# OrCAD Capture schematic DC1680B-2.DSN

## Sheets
1 Mother Board_Daughter Connect: size Custom
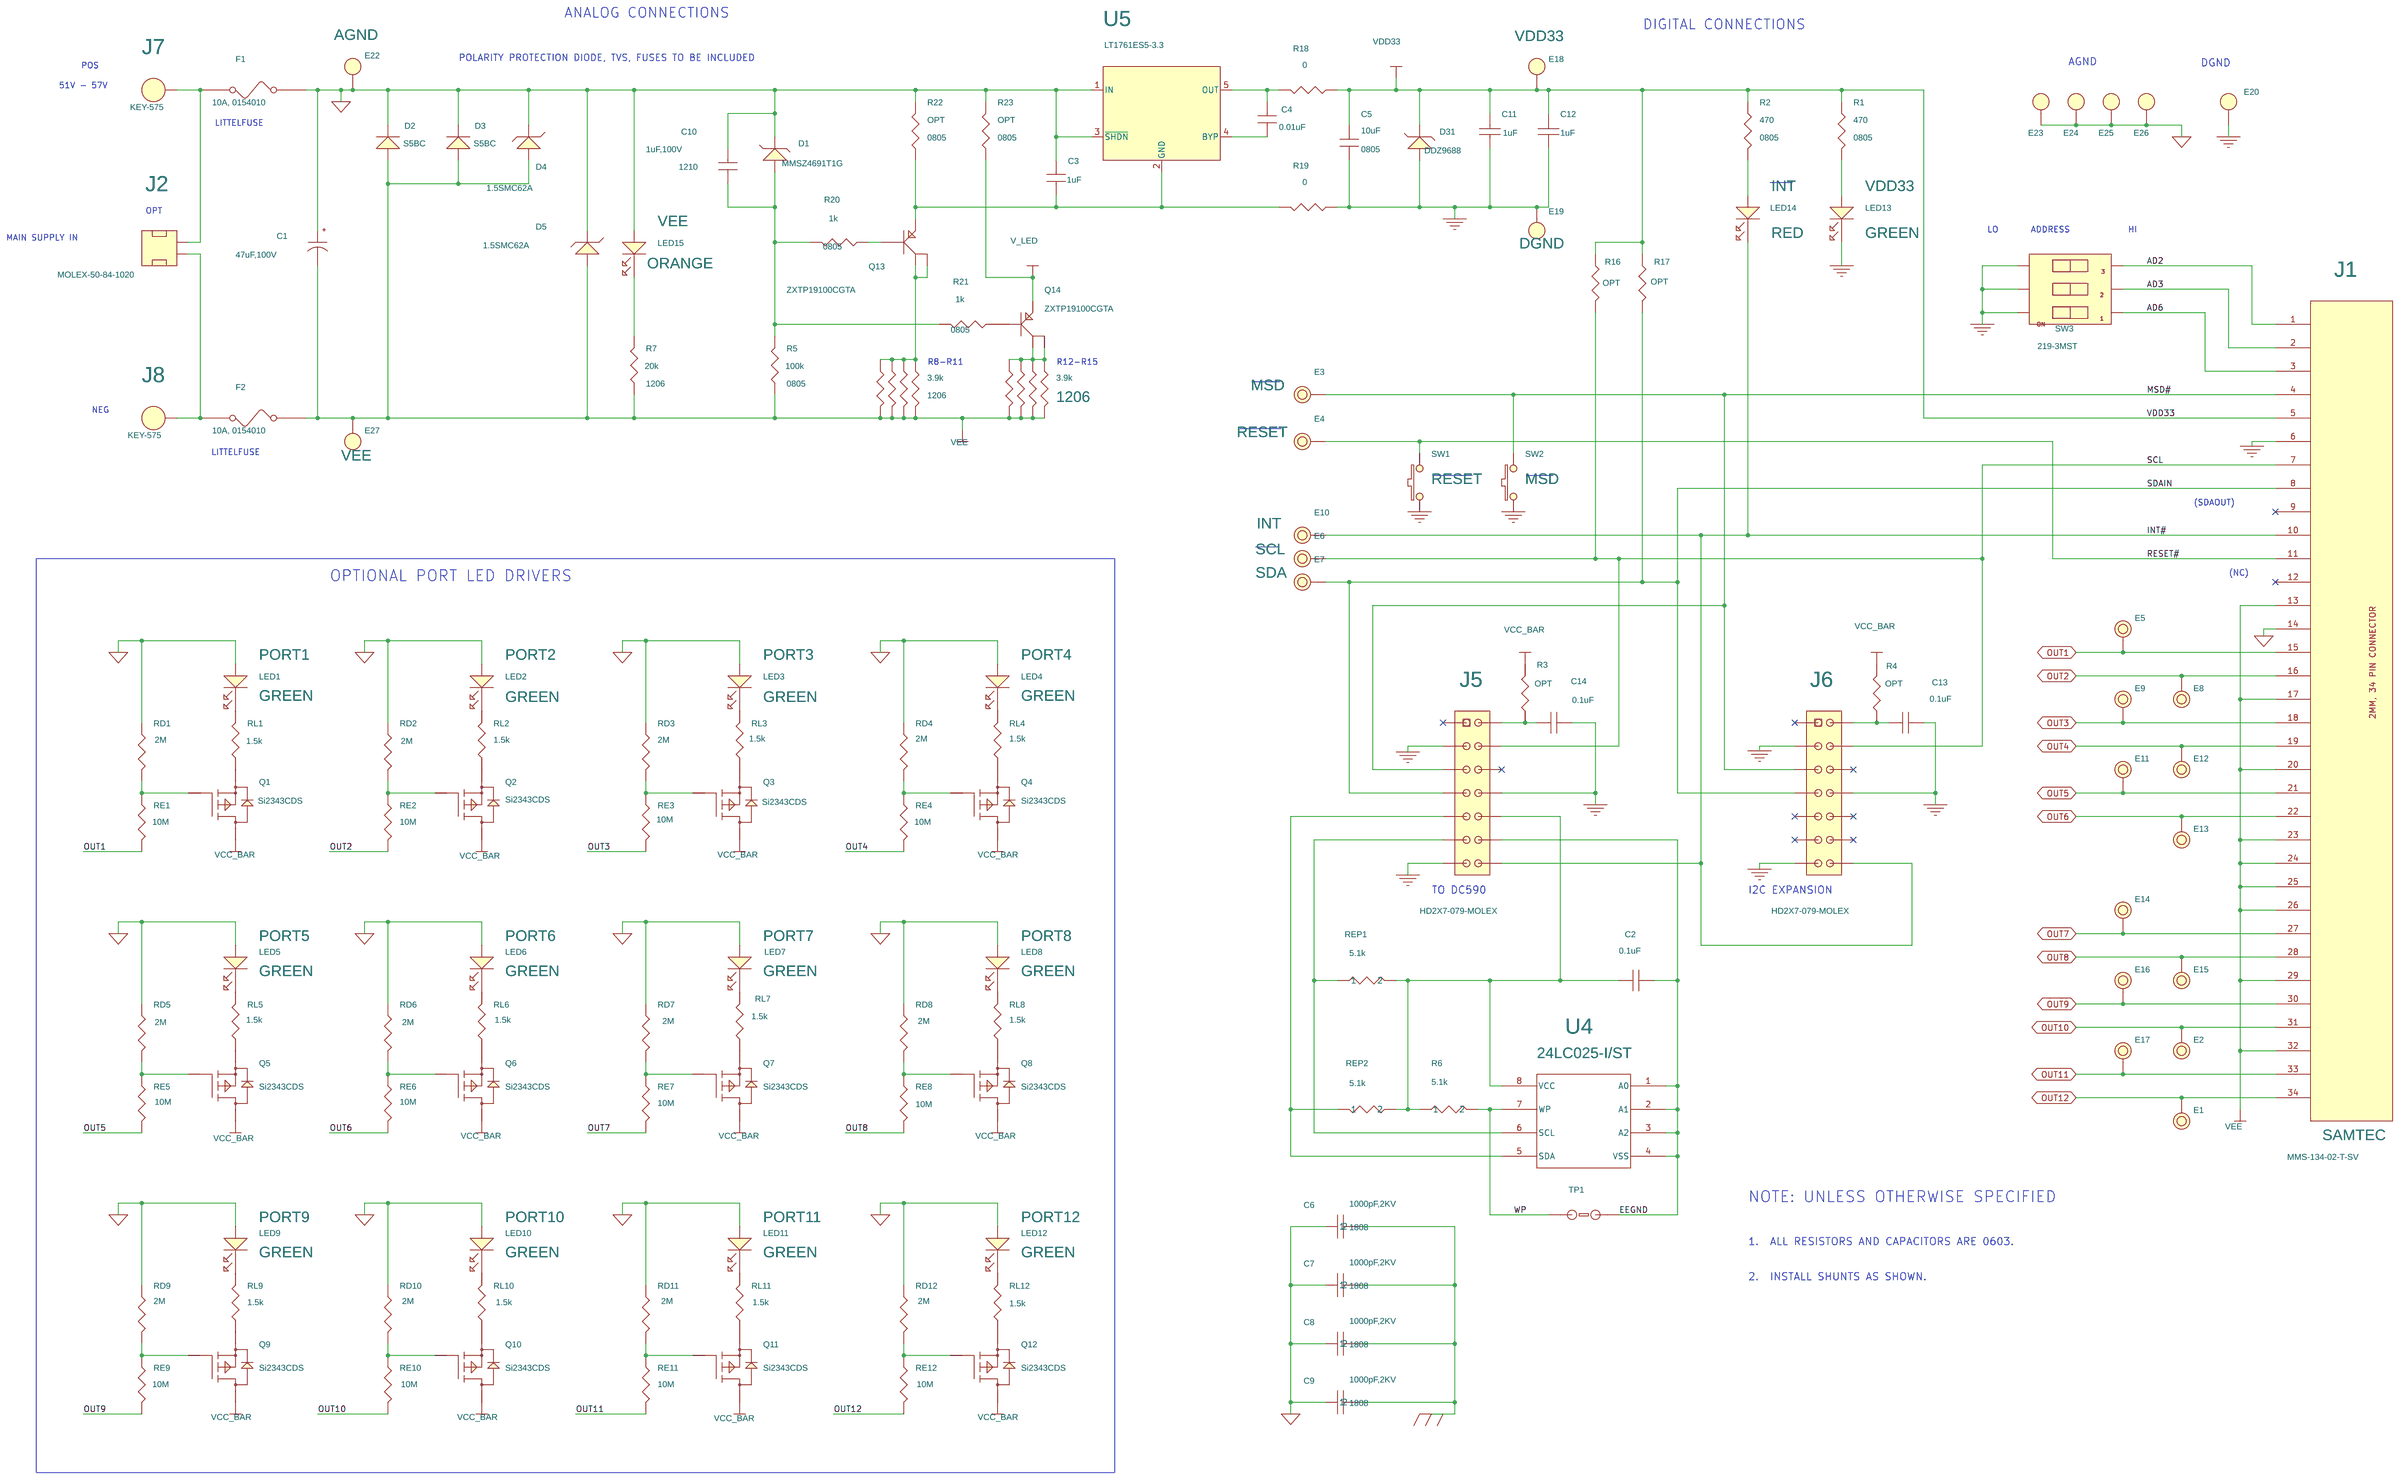
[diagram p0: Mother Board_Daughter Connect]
2 Ports 1 to 4 Jacks: size Custom; title: 12-PORT IEEE802.3at PSE MOTHER BOARD; rev: 2; note: DEMO CIRCUIT 1680B
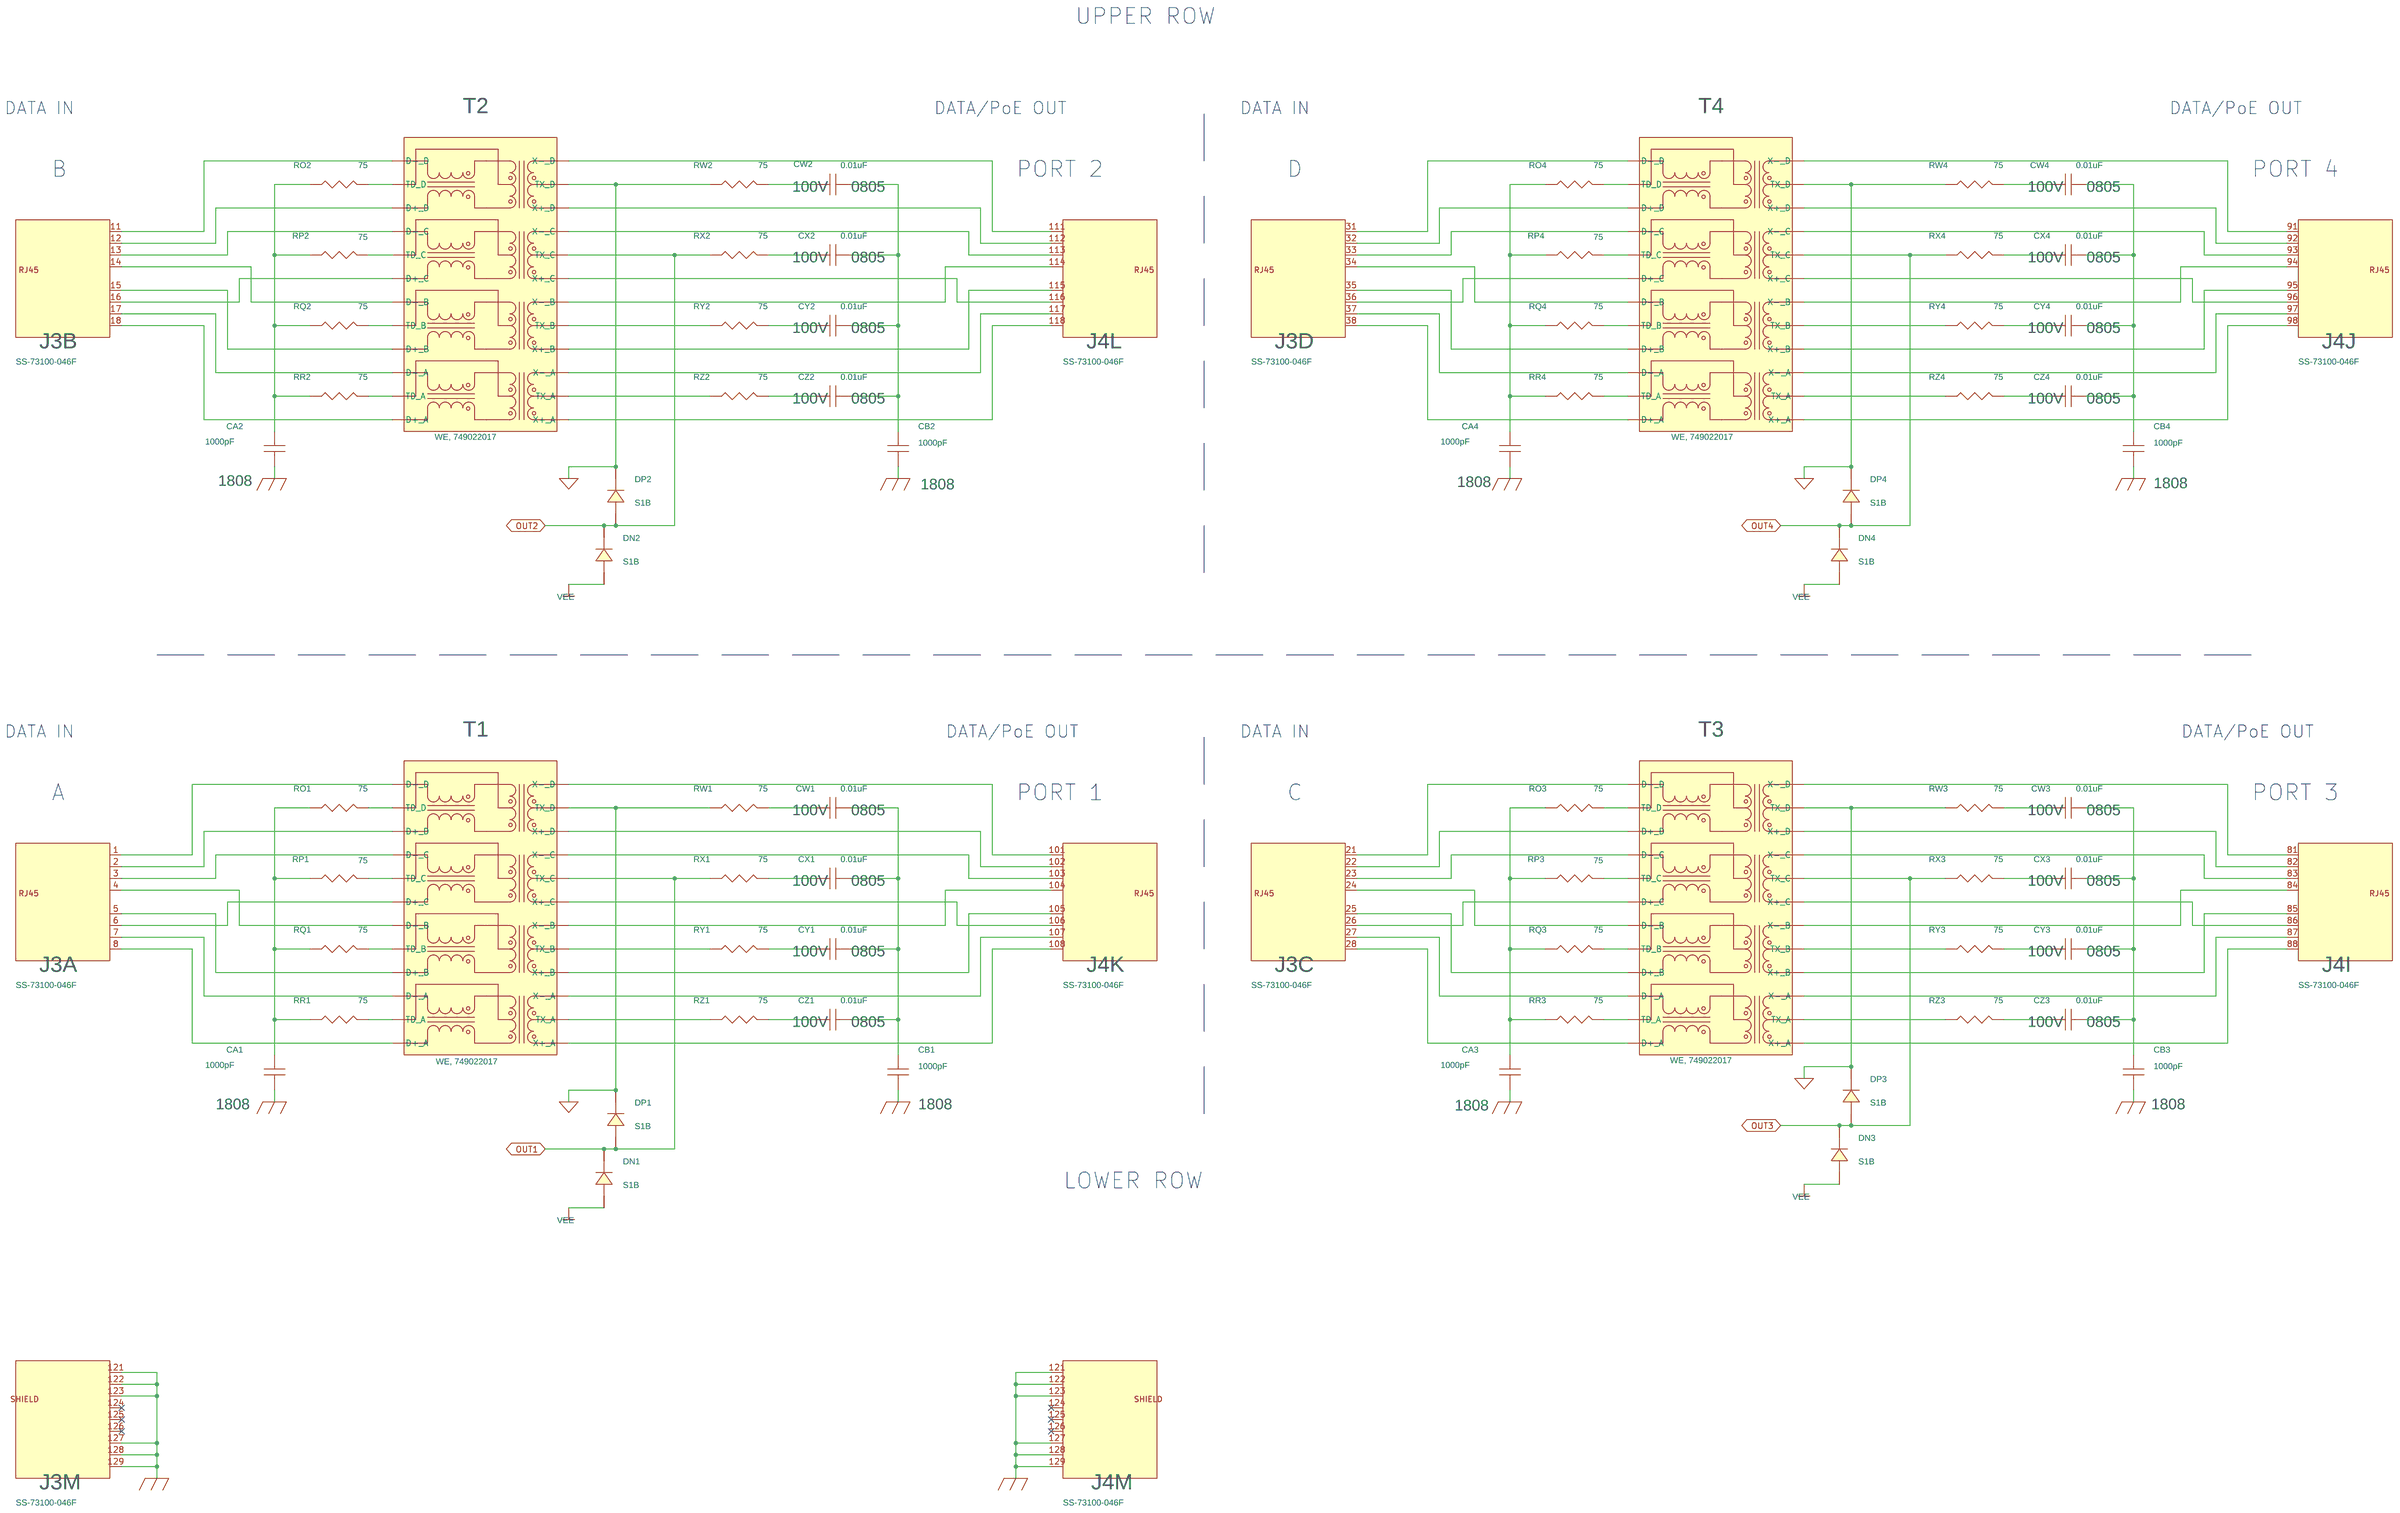
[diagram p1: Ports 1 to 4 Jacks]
3 Ports 5 to 8 Jacks: size Custom; title: 12-PORT IEEE802.3at PSE MOTHER BOARD; rev: 2; note: DEMO CIRCUIT 1680B
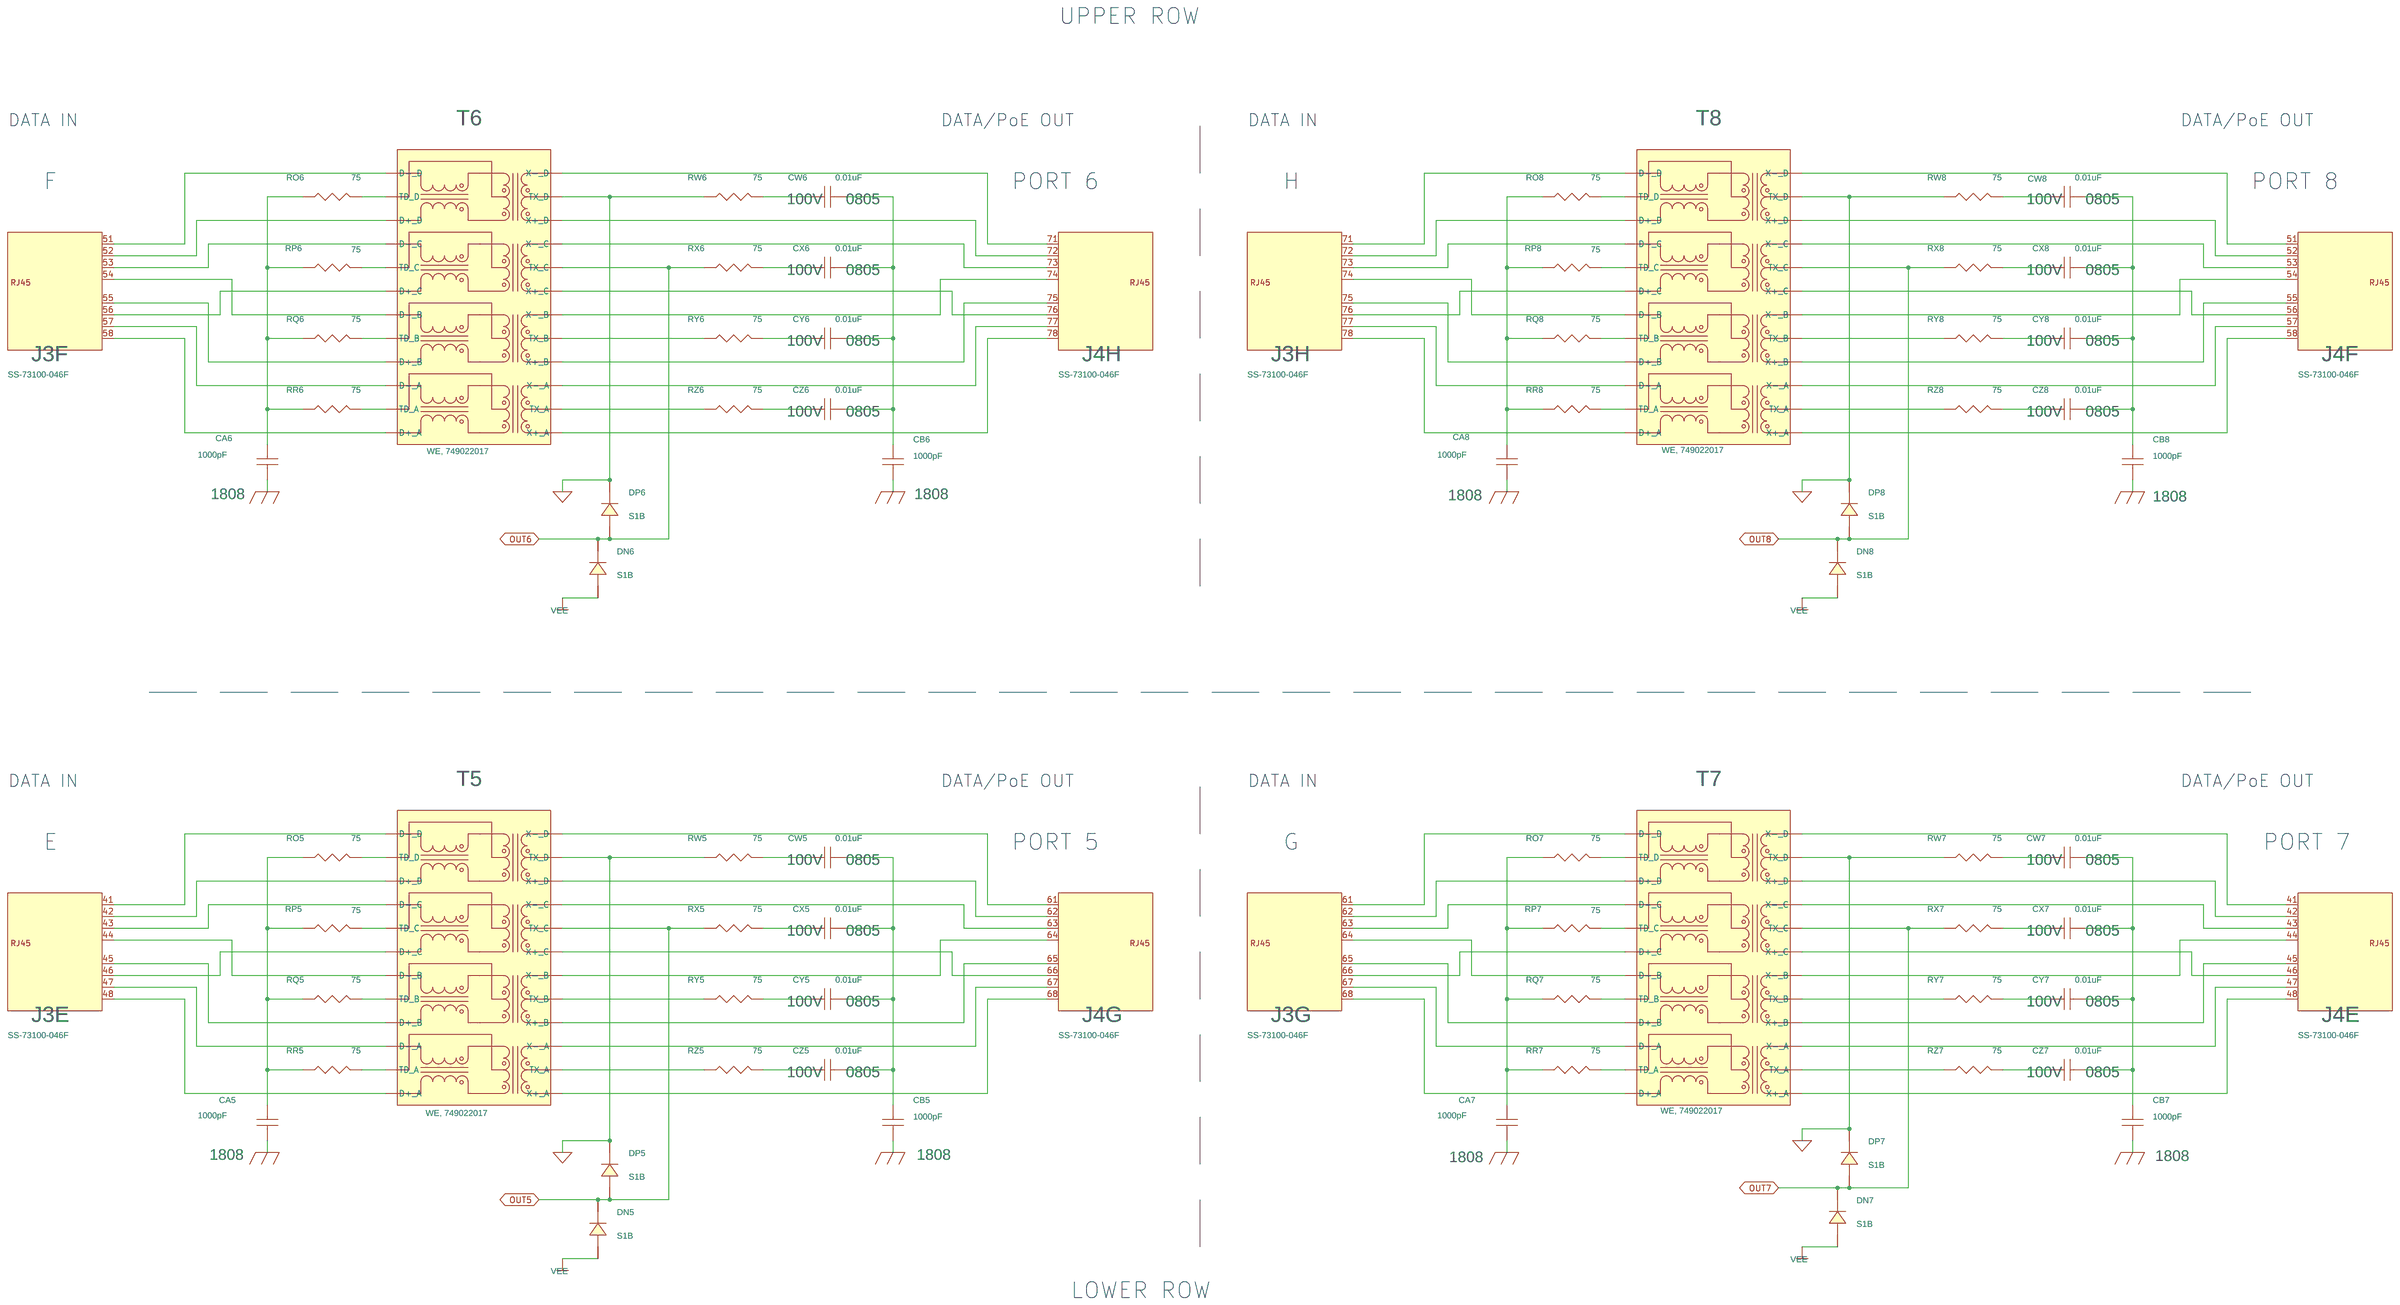
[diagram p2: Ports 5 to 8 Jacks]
4 Ports 9 to 12 Jacks: size Custom; title: 12-PORT IEEE802.3at PSE MOTHER BOARD; rev: 2; note: DEMO CIRCUIT 1680B
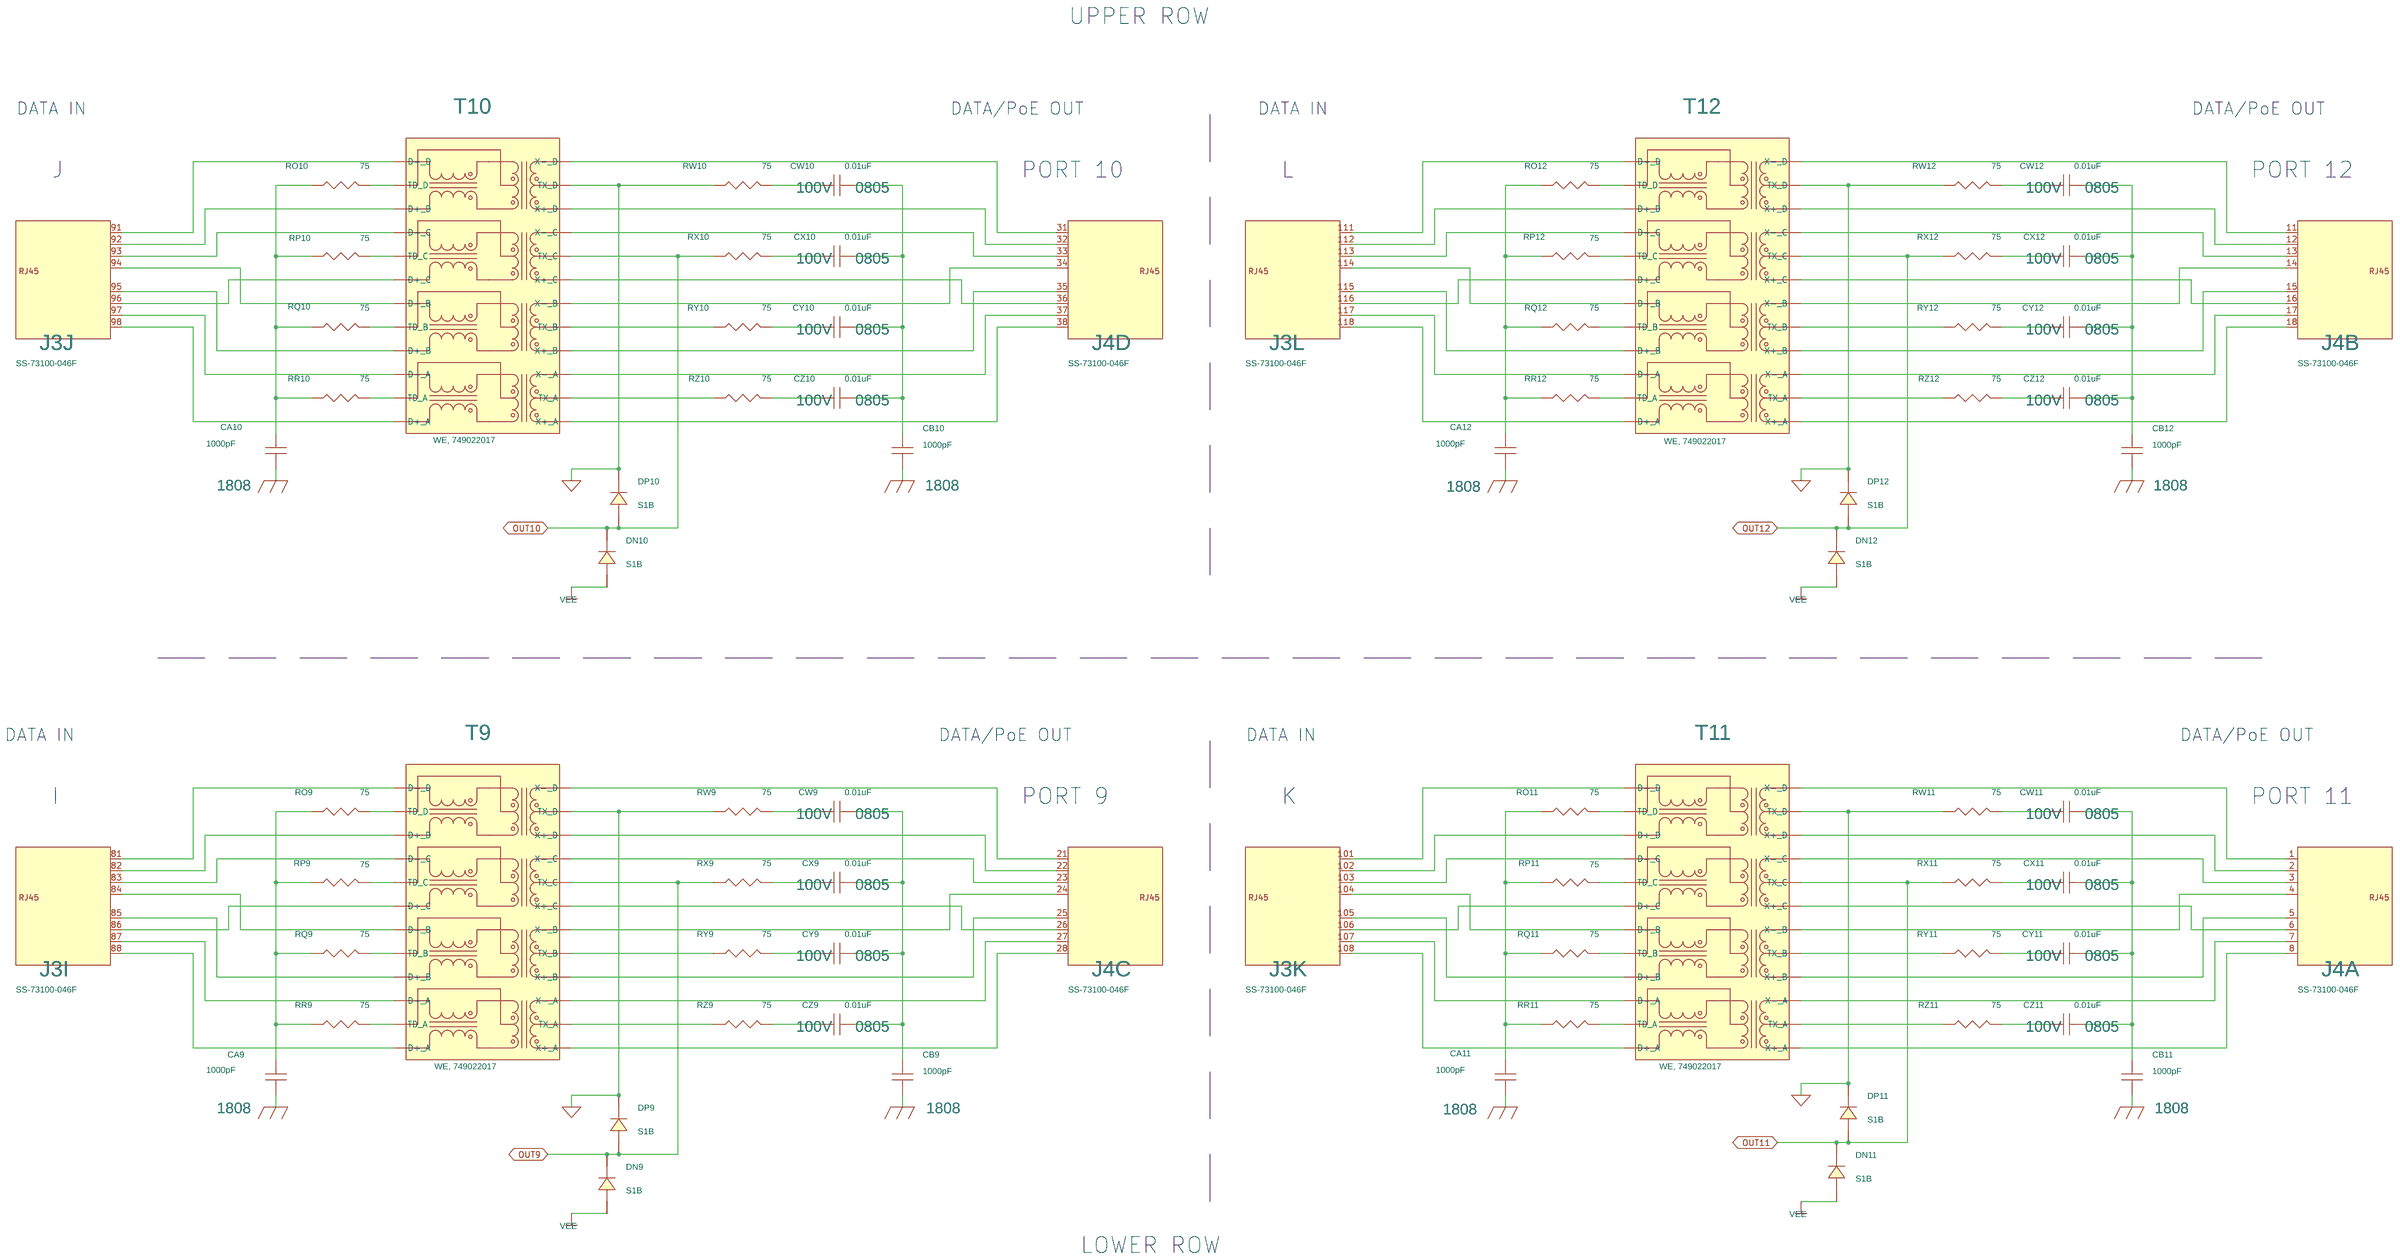
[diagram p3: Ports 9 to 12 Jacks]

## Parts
sheet Mother Board_Daughter Connect
C1  47uF,100V  [C-PANA-H13-12.5X13.5]
C2  0.1uF  [0603]
C3  1uF  [0603]
C4  0.01uF  [0603]
C5  10uF  [0805]
C6  1000pF,2KV  [1808]
C7  1000pF,2KV  [1808]
C8  1000pF,2KV  [1808]
C9  1000pF,2KV  [1808]
C10  1uF,100V  [1210]
C11  1uF  [0603]
C12  1uF  [0603]
C13  0.1uF  [0603]
C14  0.1uF  [0603]
D1  MMSZ4691T1G  [SOD123]
D2  S5BC  [SMC-DIODE]
D3  S5BC  [SMC-DIODE]
D4  1.5SMC62A  [SMC-DIODE]
D5  1.5SMC62A  [SMC-DIODE]
D31  DDZ9688  [SOD123]
E1  MILL-MAX-2308  [MILL-MAX-2308]
E2  MILL-MAX-2308  [MILL-MAX-2308]
E3  MILL-MAX-2308  [MILL-MAX-2308]
E4  MILL-MAX-2308  [MILL-MAX-2308]
E5  MILL-MAX-2308  [MILL-MAX-2308]
E6  MILL-MAX-2308  [MILL-MAX-2308]
E7  MILL-MAX-2308  [MILL-MAX-2308]
E8  MILL-MAX-2308  [MILL-MAX-2308]
E9  MILL-MAX-2308  [MILL-MAX-2308]
E10  MILL-MAX-2308  [MILL-MAX-2308]
E11  MILL-MAX-2308  [MILL-MAX-2308]
E12  MILL-MAX-2308  [MILL-MAX-2308]
E13  MILL-MAX-2308  [MILL-MAX-2308]
E14  MILL-MAX-2308  [MILL-MAX-2308]
E15  MILL-MAX-2308  [MILL-MAX-2308]
E16  MILL-MAX-2308  [MILL-MAX-2308]
E17  MILL-MAX-2308  [MILL-MAX-2308]
E18  MILL-MAX-2501  [MILL-MAX-2501]
E19  MILL-MAX-2501  [MILL-MAX-2501]
E20  MILL-MAX-2501  [MILL-MAX-2501]
E22  MILL-MAX-2501  [MILL-MAX-2501]
E23  MILL-MAX-2501  [MILL-MAX-2501]
E24  MILL-MAX-2501  [MILL-MAX-2501]
E25  MILL-MAX-2501  [MILL-MAX-2501]
E26  MILL-MAX-2501  [MILL-MAX-2501]
E27  MILL-MAX-2501  [MILL-MAX-2501]
F1  10A, 0154010  [FUSE-LITTELFUSE-154]
F2  10A, 0154010  [FUSE-LITTELFUSE-154]
J1  MMS-134-02-T-SV  [CON-MMS-134-02-T-SV]
J2  MOLEX-50-84-1020  [CON-MOLEX-50-84-1020]
J5  HD2X7-079-MOLEX  [HD2X7-079-MOLEX]
J6  HD2X7-079-MOLEX  [HD2X7-079-MOLEX]
J7  KEY-575  [KEY-575]
J8  KEY-575  [KEY-575]
LED1  SML-012P8T  [LED-ROHM-SML-01]
LED2  SML-012P8T  [LED-ROHM-SML-01]
LED3  SML-012P8T  [LED-ROHM-SML-01]
LED4  SML-012P8T  [LED-ROHM-SML-01]
LED5  SML-012P8T  [LED-ROHM-SML-01]
LED6  SML-012P8T  [LED-ROHM-SML-01]
LED7  SML-012P8T  [LED-ROHM-SML-01]
LED8  SML-012P8T  [LED-ROHM-SML-01]
LED9  SML-012P8T  [LED-ROHM-SML-01]
LED10  SML-012P8T  [LED-ROHM-SML-01]
LED11  SML-012P8T  [LED-ROHM-SML-01]
LED12  SML-012P8T  [LED-ROHM-SML-01]
LED13  SML-012P8T  [LED-ROHM-SML-01]
LED14  SML-012V8T  [LED-ROHM-SML-01]
LED15  SML-012D8T  [LED-ROHM-SML-01]
Q1  Si2343CDS  [SOT23]
Q2  Si2343CDS  [SOT23]
Q3  Si2343CDS  [SOT23]
Q4  Si2343CDS  [SOT23]
Q5  Si2343CDS  [SOT23]
Q6  Si2343CDS  [SOT23]
Q7  Si2343CDS  [SOT23]
Q8  Si2343CDS  [SOT23]
Q9  Si2343CDS  [SOT23]
Q10  Si2343CDS  [SOT23]
Q11  Si2343CDS  [SOT23]
Q12  Si2343CDS  [SOT23]
Q13  ZXTP19100CGTA  [SOT223]
Q14  ZXTP19100CGTA  [SOT223]
R1  470  [0805]
R2  470  [0805]
R3  OPT  [0603]
R4  OPT  [0603]
R5  100k  [0805]
R6  5.1k  [0603]
R7  20k  [1206]
R8  3.9k  [1206]
R9  3.9k  [1206]
R10  3.9k  [1206]
R11  3.9k  [1206]
R12  3.9k  [1206]
R13  3.9k  [1206]
R14  3.9k  [1206]
R15  3.9k  [1206]
R16  OPT  [0603]
R17  OPT  [0603]
R18  0  [0603]
R19  0  [0603]
R20  1k  [0805]
R21  1k  [0805]
R22  OPT  [0805]
R23  OPT  [0805]
RD1  2M  [0603]
RD2  2M  [0603]
RD3  2M  [0603]
RD4  2M  [0603]
RD5  2M  [0603]
RD6  2M  [0603]
RD7  2M  [0603]
RD8  2M  [0603]
RD9  2M  [0603]
RD10  2M  [0603]
RD11  2M  [0603]
RD12  2M  [0603]
RE1  10M  [0603]
RE2  10M  [0603]
RE3  10M  [0603]
RE4  10M  [0603]
RE5  10M  [0603]
RE6  10M  [0603]
RE7  10M  [0603]
RE8  10M  [0603]
RE9  10M  [0603]
RE10  10M  [0603]
RE11  10M  [0603]
RE12  10M  [0603]
REP1  5.1k  [0603]
REP2  5.1k  [0603]
RL1  1.5k  [0603]
RL2  1.5k  [0603]
RL3  1.5k  [0603]
RL4  1.5k  [0603]
RL5  1.5k  [0603]
RL6  1.5k  [0603]
RL7  1.5k  [0603]
RL8  1.5k  [0603]
RL9  1.5k  [0603]
RL10  1.5k  [0603]
RL11  1.5k  [0603]
RL12  1.5k  [0603]
SW1  SW-EVQPE1  [SW-EVQPE1]
SW2  SW-EVQPE1  [SW-EVQPE1]
SW3  219-3MST  [SW-219-3M]
TP1  SMD 2 pads  [testpad-2smd]
U4  24LC025-I/ST  [TSSOP8]
U5  LT1761ES5-3.3  [SOT23-S5]
sheet Ports 1 to 4 Jacks
CA1  1000pF  [1808]
CA2  1000pF  [1808]
CA3  1000pF  [1808]
CA4  1000pF  [1808]
CB1  1000pF  [1808]
CB2  1000pF  [1808]
CB3  1000pF  [1808]
CB4  1000pF  [1808]
CW1  0.01uF  [0805]
CW2  0.01uF  [0805]
CW3  0.01uF  [0805]
CW4  0.01uF  [0805]
CX1  0.01uF  [0805]
CX2  0.01uF  [0805]
CX3  0.01uF  [0805]
CX4  0.01uF  [0805]
CY1  0.01uF  [0805]
CY2  0.01uF  [0805]
CY3  0.01uF  [0805]
CY4  0.01uF  [0805]
CZ1  0.01uF  [0805]
CZ2  0.01uF  [0805]
CZ3  0.01uF  [0805]
CZ4  0.01uF  [0805]
DN1  S1B  [SMA-DIODE]
DN2  S1B  [SMA-DIODE]
DN3  S1B  [SMA-DIODE]
DN4  S1B  [SMA-DIODE]
DP1  S1B  [SMA-DIODE]
DP2  S1B  [SMA-DIODE]
DP3  S1B  [SMA-DIODE]
DP4  S1B  [SMA-DIODE]
RO1  75  [0603]
RO2  75  [0603]
RO3  75  [0603]
RO4  75  [0603]
RP1  75  [0603]
RP2  75  [0603]
RP3  75  [0603]
RP4  75  [0603]
RQ1  75  [0603]
RQ2  75  [0603]
RQ3  75  [0603]
RQ4  75  [0603]
RR1  75  [0603]
RR2  75  [0603]
RR3  75  [0603]
RR4  75  [0603]
RW1  75  [0603]
RW2  75  [0603]
RW3  75  [0603]
RW4  75  [0603]
RX1  75  [0603]
RX2  75  [0603]
RX3  75  [0603]
RX4  75  [0603]
RY1  75  [0603]
RY2  75  [0603]
RY3  75  [0603]
RY4  75  [0603]
RZ1  75  [0603]
RZ2  75  [0603]
RZ3  75  [0603]
RZ4  75  [0603]
T1  WE, 749022017  [TRANS-WE-749022016]
T2  WE, 749022017  [TRANS-WE-749022016]
T3  WE, 749022017  [TRANS-WE-749022016]
T4  WE, 749022017  [TRANS-WE-749022016]
sheet Ports 5 to 8 Jacks
CA5  1000pF  [1808]
CA6  1000pF  [1808]
CA7  1000pF  [1808]
CA8  1000pF  [1808]
CB5  1000pF  [1808]
CB6  1000pF  [1808]
CB7  1000pF  [1808]
CB8  1000pF  [1808]
CW5  0.01uF  [0805]
CW6  0.01uF  [0805]
CW7  0.01uF  [0805]
CW8  0.01uF  [0805]
CX5  0.01uF  [0805]
CX6  0.01uF  [0805]
CX7  0.01uF  [0805]
CX8  0.01uF  [0805]
CY5  0.01uF  [0805]
CY6  0.01uF  [0805]
CY7  0.01uF  [0805]
CY8  0.01uF  [0805]
CZ5  0.01uF  [0805]
CZ6  0.01uF  [0805]
CZ7  0.01uF  [0805]
CZ8  0.01uF  [0805]
DN5  S1B  [SMA-DIODE]
DN6  S1B  [SMA-DIODE]
DN7  S1B  [SMA-DIODE]
DN8  S1B  [SMA-DIODE]
DP5  S1B  [SMA-DIODE]
DP6  S1B  [SMA-DIODE]
DP7  S1B  [SMA-DIODE]
DP8  S1B  [SMA-DIODE]
J3  SS-73100-046F  [RJ45-DC1679-J3]  (sections A,B,C,D,E,F,G,H,I,J,K,L,M)
J4  SS-73100-046F  [RJ45-DC1679-J3]  (sections A,B,C,D,E,F,G,H,I,J,K,L,M)
RO5  75  [0603]
RO6  75  [0603]
RO7  75  [0603]
RO8  75  [0603]
RP5  75  [0603]
RP6  75  [0603]
RP7  75  [0603]
RP8  75  [0603]
RQ5  75  [0603]
RQ6  75  [0603]
RQ7  75  [0603]
RQ8  75  [0603]
RR5  75  [0603]
RR6  75  [0603]
RR7  75  [0603]
RR8  75  [0603]
RW5  75  [0603]
RW6  75  [0603]
RW7  75  [0603]
RW8  75  [0603]
RX5  75  [0603]
RX6  75  [0603]
RX7  75  [0603]
RX8  75  [0603]
RY5  75  [0603]
RY6  75  [0603]
RY7  75  [0603]
RY8  75  [0603]
RZ5  75  [0603]
RZ6  75  [0603]
RZ7  75  [0603]
RZ8  75  [0603]
T5  WE, 749022017  [TRANS-WE-749022016]
T6  WE, 749022017  [TRANS-WE-749022016]
T7  WE, 749022017  [TRANS-WE-749022016]
T8  WE, 749022017  [TRANS-WE-749022016]
sheet Ports 9 to 12 Jacks
CA9  1000pF  [1808]
CA10  1000pF  [1808]
CA11  1000pF  [1808]
CA12  1000pF  [1808]
CB9  1000pF  [1808]
CB10  1000pF  [1808]
CB11  1000pF  [1808]
CB12  1000pF  [1808]
CW9  0.01uF  [0805]
CW10  0.01uF  [0805]
CW11  0.01uF  [0805]
CW12  0.01uF  [0805]
CX9  0.01uF  [0805]
CX10  0.01uF  [0805]
CX11  0.01uF  [0805]
CX12  0.01uF  [0805]
CY9  0.01uF  [0805]
CY10  0.01uF  [0805]
CY11  0.01uF  [0805]
CY12  0.01uF  [0805]
CZ9  0.01uF  [0805]
CZ10  0.01uF  [0805]
CZ11  0.01uF  [0805]
CZ12  0.01uF  [0805]
DN9  S1B  [SMA-DIODE]
DN10  S1B  [SMA-DIODE]
DN11  S1B  [SMA-DIODE]
DN12  S1B  [SMA-DIODE]
DP9  S1B  [SMA-DIODE]
DP10  S1B  [SMA-DIODE]
DP11  S1B  [SMA-DIODE]
DP12  S1B  [SMA-DIODE]
RO9  75  [0603]
RO10  75  [0603]
RO11  75  [0603]
RO12  75  [0603]
RP9  75  [0603]
RP10  75  [0603]
RP11  75  [0603]
RP12  75  [0603]
RQ9  75  [0603]
RQ10  75  [0603]
RQ11  75  [0603]
RQ12  75  [0603]
RR9  75  [0603]
RR10  75  [0603]
RR11  75  [0603]
RR12  75  [0603]
RW9  75  [0603]
RW10  75  [0603]
RW11  75  [0603]
RW12  75  [0603]
RX9  75  [0603]
RX10  75  [0603]
RX11  75  [0603]
RX12  75  [0603]
RY9  75  [0603]
RY10  75  [0603]
RY11  75  [0603]
RY12  75  [0603]
RZ9  75  [0603]
RZ10  75  [0603]
RZ11  75  [0603]
RZ12  75  [0603]
T9  WE, 749022017  [TRANS-WE-749022016]
T10  WE, 749022017  [TRANS-WE-749022016]
T11  WE, 749022017  [TRANS-WE-749022016]
T12  WE, 749022017  [TRANS-WE-749022016]

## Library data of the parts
C1 = CAP-CE-13X13: 1ST PART FIELD: 100V
C2 C11-C14 = TMK107BJ104KL
C3 C4 = CAP0603
C5 = CAP0805
C6 = C_1
C7 = C
C8 = C_3
C9 = C_2
C10 = CAP1210: 1ST PART FIELD: 100V
D1 = DIODE-MMSZ4691T1G-SOD123
D2 D3 = DIODE-S5BC-SMC-DIODE
D4 D5 = DIODE-1.5SMC-SMC-DIODE
D31 = DIODE-DDZ9688-SOD123
E1 = E-064: PART FIELD 1: OUT12
E2 = E-064: PART FIELD 1: OUT10
E3 = E-064: PART FIELD 1: MSD
E4 = E-064: PART FIELD 1: RESET
E5 = E-064: PART FIELD 1: OUT1
E6 = E-064: PART FIELD 1: SCL
E7 = E-064: PART FIELD 1: SDA
E8 = E-064: PART FIELD 1: OUT2
E9 = E-064: PART FIELD 1: OUT3
E10 = E-064: PART FIELD 1: INT
E11 = E-064: PART FIELD 1: OUT5
E12 = E-064: PART FIELD 1: OUT4
E13 = E-064: PART FIELD 1: OUT6
E14 = E-064: PART FIELD 1: OUT7
E15 = E-064: PART FIELD 1: OUT8
E16 = E-064: PART FIELD 1: OUT9
E17 = E-064: PART FIELD 1: OUT11
E18 = E-094: 1ST PART FIELD: VDD33; PART FIELD 1: VDD33
E19 = E-094: 1ST PART FIELD: DGND; PART FIELD 1: DGND
E20 E23-E26 = E-094
E22 = E-094: PART FIELD 1: AGND
E27 = E-094: PART FIELD 1: VEE
F1 F2 = FUSE
J1 = LTC4258CGW_2: IC, LTC4266CUHF, QUAD PSE CONTROLLER; 5th Part Field: 80 Pin Edge Connector; PART FIELD 1: SAMTEC; Part Number: LINEAR TECH. LTC4266CUHF
J2 = CON-MOLEX-50-84-1020: OPT: OPT
J5 J6 = Molex-87331-1420
J7 J8 = KEY-575--4
LED1 = LED-ROHM-SML-012P8T-GREEN: PART FIELD 1: PORT1; PART FIELD 2: GREEN
LED2 = LED-ROHM-SML-012P8T-GREEN: PART FIELD 1: PORT2; PART FIELD 2: GREEN
LED3 = LED-ROHM-SML-012P8T-GREEN: PART FIELD 1: PORT3; PART FIELD 2: GREEN
LED4 = LED-ROHM-SML-012P8T-GREEN: PART FIELD 1: PORT4; PART FIELD 2: GREEN
LED5 = LED-ROHM-SML-012P8T-GREEN: PART FIELD 1: PORT5; PART FIELD 2: GREEN
LED6 = LED-ROHM-SML-012P8T-GREEN: PART FIELD 1: PORT6; PART FIELD 2: GREEN
LED7 = LED-ROHM-SML-012P8T-GREEN: PART FIELD 1: PORT7; PART FIELD 2: GREEN
LED8 = LED-ROHM-SML-012P8T-GREEN: PART FIELD 1: PORT8; PART FIELD 2: GREEN
LED9 = LED-ROHM-SML-012P8T-GREEN: PART FIELD 1: PORT9; PART FIELD 2: GREEN
LED10 = LED-ROHM-SML-012P8T-GREEN: PART FIELD 1: PORT10; PART FIELD 2: GREEN
LED11 = LED-ROHM-SML-012P8T-GREEN: PART FIELD 1: PORT11; PART FIELD 2: GREEN
LED12 = LED-ROHM-SML-012P8T-GREEN: PART FIELD 1: PORT12; PART FIELD 2: GREEN
LED13 = LED-ROHM-SML-012P8T-GREEN: PART FIELD 1: VDD33; PART FIELD 2: GREEN
LED14 = LED-ROHM-SML-012V8T-RED: PART FIELD 1: INT; PART FIELD 2: RED
LED15 = LED-ROHM-SML-012D8T-ORANGE: PART FIELD 1: VEE; PART FIELD 2: ORANGE
Q1-Q12 = MOSFET_P-Si2343CDS-SOT23
Q13 Q14 = PNP-ZXTP19100CG-SOT223
R1 R2 R5 R22 R23 = AAC-0805: 4TH PART FIELD: VISHAY,
R3 R4 = R
R6 = CR16-4991FM_2: 2nd Part Field: 5%
R7 = AAC-0805: 2ND PART FIELD: 0805; 4TH PART FIELD: VISHAY,
R8-R15 = AAC-1206: 4TH PART FIELD: VISHAY,
R16 = CR16-1104FM_9
R17 = CR16-1104FM
R18 R19 RL1-RL12 = CR16-301JM
R20 R21 = AAC-0805: 4th Part Field: VISHAY,
RD1 = CR16-1104FM_3
RD2 = CR16-1104FM_20
RD3 = CR16-1104FM_6
RD4 = CR16-1104FM_11
RD5 = CR16-1104FM_17
RD6 = CR16-1104FM_21
RD7 = CR16-1104FM_1
RD8 = CR16-1104FM_24
RD9 = CR16-1104FM_8
RD10 = CR16-1104FM_23
RD11 = CR16-1104FM_25
RD12 = CR16-1104FM_12
RE1 = CR16-1104FM_18
RE2 = CR16-1104FM_13
RE3 = CR16-1104FM_2
RE4 = CR16-1104FM_5
RE5 = CR16-1104FM_7
RE6 = CR16-1104FM_14
RE7 = CR16-1104FM_19
RE8 = CR16-1104FM_4
RE9 = CR16-1104FM_10
RE10 = CR16-1104FM_22
RE11 = CR16-1104FM_16
RE12 = CR16-1104FM_15
REP1 = CR16-4991FM_1: 2nd Part Field: 5%
REP2 = CR16-4991FM: 2nd Part Field: 5%
SW1 = SW_PB_SPST: 5TH PART FIELD: PANASONIC, EVQPE105K; PART FIELD 1: RESET
SW2 = SW_PB_SPST: 5TH PART FIELD: PANASONIC, EVQPE105K; PART FIELD 1: MSD
SW3 = SW-219-3M_0
TP1 = testpad-2smd
U4 = 24LC025
U5 = LT1761ES5--3_1.3
CA1-CA12 CB1-CB12 = C4520X7R3D102M: CAP, 1808 1000pF 10% 2KV X7R; Part Number: TDK C4520X7R3D102K
CW1-CW12 CX1-CX12 CY1-CY12 CZ1-CZ12 = CAP_NP: CAP, 0805 0.01uF 5% 100V X7R; Part Number: AVX 0805C103JAT2A; VOLTAGE: 100V
DN1-DN12 DP1-DP12 = S1A-S1M_0
RO1-RO12 RP1-RP12 RQ1-RQ12 RR1-RR12 RW1-RW12 RX1-RX12 RY1-RY12 RZ1-RZ12 = CR16-750JM: RES, 0603 75 OHMS 5% 1/10W; Part Number: VISHAY CRCW060375R0JNEA
T1-T12 = TRANS-DA2125_1: TRANSFORMER, POE++ 70W; Part Number: MIDCOM WURTH 749022016
J3 J4 = RJ45-SS-73100-046F

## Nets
Agnd: C1.1 C3.1 C6.1 C7.1 C8.1 C9.1 C10.1 D1.1 D2.1 D3.1 D4.1 D5.1 DP1.1 DP2.1 DP3.1 DP4.1 DP5.1 DP6.1 DP7.1 DP8.1 DP9.1 DP10.1 DP11.1 DP12.1 E22.1(A) E23.1(A) E24.1(A) E25.1(A) E26.1(A) F1.1 J1.14 LED1.1 LED2.1 LED3.1 LED4.1 LED5.1 LED6.1 LED7.1 LED8.1 LED9.1 LED10.1 LED11.1 LED12.1 LED15.1 R22.2 R23.2 RD1.1 RD2.1 RD3.1 RD4.1 RD5.1 RD6.1 RD7.1 RD8.1 RD9.1 RD10.1 RD11.1 RD12.1 RW1.2 RW2.2 RW3.2 RW4.2 RW5.2 RW6.2 RW7.2 RW8.2 RW9.2 RW10.2 RW11.2 RW12.2 T1.15(TX_D) T2.15(TX_D) T3.15(TX_D) T4.15(TX_D) T5.15(TX_D) T6.15(TX_D) T7.15(TX_D) T8.15(TX_D) T9.15(TX_D) T10.15(TX_D) T11.15(TX_D) T12.15(TX_D) U5.1(IN) U5.3(~{SHDN})
GND: C5.2 C11.1 C12.1 C13.2 C14.2 D31.2 E19.1(A) E20.1(A) J1.6 J5.3 J5.8 J5.13 J6.3 J6.8 J6.13 LED13.2 R19.1 SW1.1 SW2.1 SW3.4 SW3.5 SW3.6
GND_EARTH: CA1.2 CA2.2 CA3.2 CA4.2 CA5.2 CA6.2 CA7.2 CA8.2 CA9.2 CA10.2 CA11.2 CA12.2 CB1.2 CB2.2 CB3.2 CB4.2 CB5.2 CB6.2 CB7.2 CB8.2 CB9.2 CB10.2 CB11.2 CB12.2
VDD33: C5.1 C11.2 C12.2 D31.1 E18.1(A) J1.5 R1.1 R2.1 R3.2 R4.2 R16.1 R17.1 R18.1
VEE: C1.2 D2.2 D3.2 D4.2 D5.2 DN1.2 DN2.2 DN3.2 DN4.2 DN5.2 DN6.2 DN7.2 DN8.2 DN9.2 DN10.2 DN11.2 DN12.2 E27.1(A) F2.1 J1.13 J1.17 J1.20 J1.23 J1.24 J1.25 J1.26 J1.29 J1.32 R5.1 R7.1 R8.2 R9.2 R10.2 R11.2 R12.2 R13.2 R14.2 R15.2
AD2: J1.1 SW3.3
AD3: J1.2 SW3.2
AD6: J1.3 SW3.1
CGND: C6.2 C7.2 C8.2 C9.2 J3.121 J3.122 J3.123 J3.127 J3.128 J3.129 J4.121 J4.122 J4.123 J4.127 J4.128 J4.129
EEGND: C2.2 J5.12 TP1.2 U4.1(A0) U4.2(A1) U4.3(A2) U4.4(VSS)
INT#: E10.1(A) J1.10 J5.14 J6.14 LED14.2
MSD#: E3.1(A) J1.4 J5.5 J6.5 SW2.2
OUT1: DN1.1 DP1.2 E5.1(A) J1.15 RE1.2 RX1.2 T1.18(TX_C)
OUT2: DN2.1 DP2.2 E8.1(A) J1.16 RE2.2 RX2.2 T2.18(TX_C)
OUT3: DN3.1 DP3.2 E9.1(A) J1.18 RE3.2 RX3.2 T3.18(TX_C)
OUT4: DN4.1 DP4.2 E12.1(A) J1.19 RE4.2 RX4.2 T4.18(TX_C)
OUT5: DN5.1 DP5.2 E11.1(A) J1.21 RE5.2 RX5.2 T5.18(TX_C)
OUT6: DN6.1 DP6.2 E13.1(A) J1.22 RE6.2 RX6.2 T6.18(TX_C)
OUT7: DN7.1 DP7.2 E14.1(A) J1.27 RE7.2 RX7.2 T7.18(TX_C)
OUT8: DN8.1 DP8.2 E15.1(A) J1.28 RE8.2 RX8.2 T8.18(TX_C)
OUT9: DN9.1 DP9.2 E16.1(A) J1.30 RE9.2 RX9.2 T9.18(TX_C)
OUT10: DN10.1 DP10.2 E2.1(A) J1.31 RE10.2 RX10.2 T10.18(TX_C)
OUT11: DN11.1 DP11.2 E17.1(A) J1.33 RE11.2 RX11.2 T11.18(TX_C)
OUT12: DN12.1 DP12.2 E1.1(A) J1.34 RE12.2 RX12.2 T12.18(TX_C)
RESET#: E4.1(A) J1.11 SW1.2
SCL: E6.1(A) J1.7 J5.4 J6.4 R16.2
SDAIN: E7.1(A) J1.8 J5.7 J6.7 R17.2
V_LED: Q1.3 Q2.3 Q3.3 Q4.3 Q5.3 Q6.3 Q7.3 Q8.3 Q9.3 Q10.3 Q11.3 Q12.3 Q14.3 R23.1
WP: R6.2 TP1.1 U4.7(WP)
N18007586: F1.2 J2.1 J7.1
N18007733: LED14.1 R2.2
N18007735: LED13.1 R1.2
N18007745: J5.11 REP1.1 U4.6(SCL)
N18007749: C2.1 J5.10 R6.1 REP1.2 REP2.2 U4.8(VCC)
N18007753: J5.9 REP2.1 U4.5(SDA)
N18008599: Q4.1 RD4.2 RE4.1
N18008716: Q6.1 RD6.2 RE6.1
N18008760: Q7.1 RD7.2 RE7.1
N18008821: Q8.1 RD8.2 RE8.1
N18008978: Q9.1 RD9.2 RE9.1
N18009091: Q11.1 RD11.2 RE11.1
N18009454: C10.2 D1.2 R5.2 R20.2 R21.2
N18009474: F2.2 J2.2 J8.1
N18330809: C3.2 Q13.3 R19.2 R22.1 U5.2(GND)
N18333266: C4.2 U5.4(BYP)
N18470872: J3.1 T1.12(D-_D)
N18471112: J3.4 T1.6(D-_B)
N18471283: J3.6 T1.8(D+_C)
N18471462: J3.5 T1.5(D+_B)
N18471554: J3.7 T1.3(D-_A)
N18471839: J3.8 T1.2(D+_A)
N18928301: Q13.2 Q13.4 R8.1 R9.1 R10.1 R11.1
N18933108: Q14.2 Q14.4 R12.1 R13.1 R14.1 R15.1
N19160521: C14.1 J5.2 R3.1
N19302650: LED15.2 R7.2
N19344877: C13.1 J6.2 R4.1
N19344913: C4.1 R18.2 U5.5(OUT)
N19720488: RO1.1 T1.10(TD_D)
N19720490: RP1.1 T1.7(TD_C)
N19720494: RQ1.1 T1.4(TD_B)
N19720496: RR1.1 T1.1(TD_A)
N19720513: RZ1.2 T1.24(TX_A)
N19720517: J4.108 T1.23(X+_A)
N19720523: J4.105 T1.20(X+_B)
N19720525: J4.102 T1.14(X+_D)
N19720527: CB1.1 CW1.2 CX1.2 CY1.2 CZ1.2
N19720533: J4.103 T1.16(X-_C)
N19720543: J4.107 T1.22(X-_A)
N19720551: RY1.2 T1.21(TX_B)
N19720565: J3.3 T1.9(D-_C)
N19720607: CW1.1 RW1.1
N19720609: CY1.1 RY1.1
N19720611: CX1.1 RX1.1
N19720613: CZ1.1 RZ1.1
N19720638: CA1.1 RO1.2 RP1.2 RQ1.2 RR1.2
N19725411: J3.2 T1.11(D+_D)
N19807268: J4.101 T1.13(X-_D)
N19809992: J4.106 T1.17(X+_C)
N19811966: J4.104 T1.19(X-_B)
N19903688: J3.24 T3.6(D-_B)
N19903690: J3.26 T3.8(D+_C)
N19903696: J3.25 T3.5(D+_B)
N19903698: J3.27 T3.3(D-_A)
N19903700: J3.28 T3.2(D+_A)
N19903728: J4.81 T3.13(X-_D)
N19903743: J4.82 T3.14(X+_D)
N19903760: J4.83 T3.16(X-_C)
N19903762: J4.86 T3.17(X+_C)
N19903777: CB3.1 CW3.2 CX3.2 CY3.2 CZ3.2
N19903819: RO3.1 T3.10(TD_D)
N19903821: RP3.1 T3.7(TD_C)
N19903823: RQ3.1 T3.4(TD_B)
N19903825: RR3.1 T3.1(TD_A)
N19903839: RZ3.2 T3.24(TX_A)
N19903841: J4.88 T3.23(X+_A)
N19903843: J4.85 T3.20(X+_B)
N19903866: J4.87 T3.22(X-_A)
N19903868: RY3.2 T3.21(TX_B)
N19903878: J3.23 T3.9(D-_C)
N19903884: CW3.1 RW3.1
N19903886: CY3.1 RY3.1
N19903888: CX3.1 RX3.1
N19903890: CZ3.1 RZ3.1
N19903892: CA3.1 RO3.2 RP3.2 RQ3.2 RR3.2
N19903982: J4.84 T3.19(X-_B)
N19904020: J3.22 T3.11(D+_D)
N19904032: J3.21 T3.12(D-_D)
N19913165: J3.14 T2.6(D-_B)
N19913167: J3.16 T2.8(D+_C)
N19913173: J3.15 T2.5(D+_B)
N19913175: J3.17 T2.3(D-_A)
N19913177: J3.18 T2.2(D+_A)
N19913205: J4.111 T2.13(X-_D)
N19913220: J4.112 T2.14(X+_D)
N19913237: J4.113 T2.16(X-_C)
N19913239: J4.116 T2.17(X+_C)
N19913254: CB2.1 CW2.2 CX2.2 CY2.2 CZ2.2
N19913296: RO2.1 T2.10(TD_D)
N19913298: RP2.1 T2.7(TD_C)
N19913300: RQ2.1 T2.4(TD_B)
N19913302: RR2.1 T2.1(TD_A)
N19913316: RZ2.2 T2.24(TX_A)
N19913318: J4.118 T2.23(X+_A)
N19913320: J4.115 T2.20(X+_B)
N19913343: J4.117 T2.22(X-_A)
N19913345: RY2.2 T2.21(TX_B)
N19913355: J3.13 T2.9(D-_C)
N19913361: CW2.1 RW2.1
N19913363: CY2.1 RY2.1
N19913365: CZ2.1 RZ2.1
N19913367: CA2.1 RO2.2 RP2.2 RQ2.2 RR2.2
N19913375: CX2.1 RX2.1
N19913459: J4.114 T2.19(X-_B)
N19913497: J3.12 T2.11(D+_D)
N19913509: J3.11 T2.12(D-_D)
N19917611: J3.34 T4.6(D-_B)
N19917613: J3.36 T4.8(D+_C)
N19917619: J3.35 T4.5(D+_B)
N19917621: J3.37 T4.3(D-_A)
N19917623: J3.38 T4.2(D+_A)
N19917651: J4.91 T4.13(X-_D)
N19917657: J4.92 T4.14(X+_D)
N19917683: J4.93 T4.16(X-_C)
N19917685: J4.96 T4.17(X+_C)
N19917700: CB4.1 CW4.2 CX4.2 CY4.2 CZ4.2
N19917736: RO4.1 T4.10(TD_D)
N19917738: RP4.1 T4.7(TD_C)
N19917740: RQ4.1 T4.4(TD_B)
N19917748: RR4.1 T4.1(TD_A)
N19917754: RZ4.2 T4.24(TX_A)
N19917764: J4.98 T4.23(X+_A)
N19917766: J4.95 T4.20(X+_B)
N19917789: J4.97 T4.22(X-_A)
N19917791: RY4.2 T4.21(TX_B)
N19917801: J3.33 T4.9(D-_C)
N19917807: CW4.1 RW4.1
N19917809: CY4.1 RY4.1
N19917811: CX4.1 RX4.1
N19917815: CA4.1 RO4.2 RP4.2 RQ4.2 RR4.2
N19917905: J4.94 T4.19(X-_B)
N19917943: J3.32 T4.11(D+_D)
N19917955: J3.31 T4.12(D-_D)
N19950966: J3.44 T5.6(D-_B)
N19950968: J3.46 T5.8(D+_C)
N19950974: J3.45 T5.5(D+_B)
N19950976: J3.47 T5.3(D-_A)
N19950978: J3.48 T5.2(D+_A)
N19951006: J4.61 T5.13(X-_D)
N19951012: J4.62 T5.14(X+_D)
N19951038: J4.63 T5.16(X-_C)
N19951040: J4.66 T5.17(X+_C)
N19951055: CB5.1 CW5.2 CX5.2 CY5.2 CZ5.2
N19951091: RO5.1 T5.10(TD_D)
N19951093: RP5.1 T5.7(TD_C)
N19951095: RQ5.1 T5.4(TD_B)
N19951103: RR5.1 T5.1(TD_A)
N19951109: RZ5.2 T5.24(TX_A)
N19951119: J4.68 T5.23(X+_A)
N19951121: J4.65 T5.20(X+_B)
N19951144: J4.67 T5.22(X-_A)
N19951146: RY5.2 T5.21(TX_B)
N19951156: J3.43 T5.9(D-_C)
N19951162: CW5.1 RW5.1
N19951164: CY5.1 RY5.1
N19951166: CX5.1 RX5.1
N19951168: CZ5.1 RZ5.1
N19951170: CA5.1 RO5.2 RP5.2 RQ5.2 RR5.2
N19951260: J4.64 T5.19(X-_B)
N19951298: J3.42 T5.11(D+_D)
N19951310: J3.41 T5.12(D-_D)
N19956338: J3.54 T6.6(D-_B)
N19956340: J3.56 T6.8(D+_C)
N19956346: J3.55 T6.5(D+_B)
N19956348: J3.57 T6.3(D-_A)
N19956350: J3.58 T6.2(D+_A)
N19956370: J4.71 T6.13(X-_D)
N19956384: J4.72 T6.14(X+_D)
N19956401: J4.73 T6.16(X-_C)
N19956412: J4.76 T6.17(X+_C)
N19956418: CB6.1 CW6.2 CX6.2 CY6.2 CZ6.2
N19956463: RO6.1 T6.10(TD_D)
N19956465: RP6.1 T6.7(TD_C)
N19956467: RQ6.1 T6.4(TD_B)
N19956469: RR6.1 T6.1(TD_A)
N19956481: RZ6.2 T6.24(TX_A)
N19956483: J4.78 T6.23(X+_A)
N19956493: J4.75 T6.20(X+_B)
N19956516: J4.77 T6.22(X-_A)
N19956518: RY6.2 T6.21(TX_B)
N19956528: J3.53 T6.9(D-_C)
N19956534: CW6.1 RW6.1
N19956536: CY6.1 RY6.1
N19956538: CX6.1 RX6.1
N19956540: CZ6.1 RZ6.1
N19956542: CA6.1 RO6.2 RP6.2 RQ6.2 RR6.2
N19956632: J4.74 T6.19(X-_B)
N19956670: J3.52 T6.11(D+_D)
N19956676: J3.51 T6.12(D-_D)
N19965383: J3.64 T7.6(D-_B)
N19965385: J3.66 T7.8(D+_C)
N19965391: J3.65 T7.5(D+_B)
N19965393: J3.67 T7.3(D-_A)
N19965395: J3.68 T7.2(D+_A)
N19965415: J4.41 T7.13(X-_D)
N19965429: J4.42 T7.14(X+_D)
N19965446: J4.43 T7.16(X-_C)
N19965457: J4.46 T7.17(X+_C)
N19965463: CB7.1 CW7.2 CX7.2 CY7.2 CZ7.2
N19965508: RO7.1 T7.10(TD_D)
N19965510: RP7.1 T7.7(TD_C)
N19965512: RQ7.1 T7.4(TD_B)
N19965514: RR7.1 T7.1(TD_A)
N19965526: RZ7.2 T7.24(TX_A)
N19965528: J4.48 T7.23(X+_A)
N19965538: J4.45 T7.20(X+_B)
N19965561: J4.47 T7.22(X-_A)
N19965563: RY7.2 T7.21(TX_B)
N19965573: J3.63 T7.9(D-_C)
N19965579: CW7.1 RW7.1
N19965581: CY7.1 RY7.1
N19965583: CX7.1 RX7.1
N19965585: CZ7.1 RZ7.1
N19965587: CA7.1 RO7.2 RP7.2 RQ7.2 RR7.2
N19965677: J4.44 T7.19(X-_B)
N19965715: J3.62 T7.11(D+_D)
N19965721: J3.61 T7.12(D-_D)
N20002871: J3.78 T8.2(D+_A)
N20002875: J4.51 T8.13(X-_D)
N20002889: J4.52 T8.14(X+_D)
N20002901: J3.74 T8.6(D-_B)
N20002903: J3.75 T8.5(D+_B)
N20002905: J4.53 T8.16(X-_C)
N20002916: J4.56 T8.17(X+_C)
N20002922: CB8.1 CW8.2 CX8.2 CY8.2 CZ8.2
N20002968: RO8.1 T8.10(TD_D)
N20002970: RP8.1 T8.7(TD_C)
N20002972: RQ8.1 T8.4(TD_B)
N20002982: RR8.1 T8.1(TD_A)
N20002988: RZ8.2 T8.24(TX_A)
N20002990: J4.58 T8.23(X+_A)
N20002998: J4.55 T8.20(X+_B)
N20003029: J4.57 T8.22(X-_A)
N20003031: RY8.2 T8.21(TX_B)
N20003039: J3.73 T8.9(D-_C)
N20003041: J3.76 T8.8(D+_C)
N20003047: CW8.1 RW8.1
N20003049: CY8.1 RY8.1
N20003051: CX8.1 RX8.1
N20003053: CZ8.1 RZ8.1
N20003055: CA8.1 RO8.2 RP8.2 RQ8.2 RR8.2
N20003145: J4.54 T8.19(X-_B)
N20003175: J3.72 T8.11(D+_D)
N20003189: J3.71 T8.12(D-_D)
N20003251: J3.77 T8.3(D-_A)
N20490037: J3.108 T11.2(D+_A)
N20490041: J4.1 T11.13(X-_D)
N20490047: J4.2 T11.14(X+_D)
N20490051: J3.104 T11.6(D-_B)
N20490053: J3.105 T11.5(D+_B)
N20490055: J4.3 T11.16(X-_C)
N20490066: J4.6 T11.17(X+_C)
N20490080: CB11.1 CW11.2 CX11.2 CY11.2 CZ11.2
N20490118: RO11.1 T11.10(TD_D)
N20490120: RP11.1 T11.7(TD_C)
N20490122: RQ11.1 T11.4(TD_B)
N20490132: RR11.1 T11.1(TD_A)
N20490138: RZ11.2 T11.24(TX_A)
N20490140: J4.8 T11.23(X+_A)
N20490144: J4.5 T11.20(X+_B)
N20490176: J4.7 T11.22(X-_A)
N20490178: RY11.2 T11.21(TX_B)
N20490205: J3.103 T11.9(D-_C)
N20490207: J3.106 T11.8(D+_C)
N20490211: CW11.1 RW11.1
N20490213: CY11.1 RY11.1
N20490215: CX11.1 RX11.1
N20490217: CZ11.1 RZ11.1
N20490219: CA11.1 RO11.2 RP11.2 RQ11.2 RR11.2
N20490311: J4.4 T11.19(X-_B)
N20490333: J3.102 T11.11(D+_D)
N20490339: J3.101 T11.12(D-_D)
N20490381: J3.107 T11.3(D-_A)
N20490416: J3.88 T9.2(D+_A)
N20490420: J4.21 T9.13(X-_D)
N20490426: J4.22 T9.14(X+_D)
N20490438: J3.84 T9.6(D-_B)
N20490440: J3.85 T9.5(D+_B)
N20490442: J4.23 T9.16(X-_C)
N20490461: J4.26 T9.17(X+_C)
N20490467: CB9.1 CW9.2 CX9.2 CY9.2 CZ9.2
N20490505: RO9.1 T9.10(TD_D)
N20490507: RP9.1 T9.7(TD_C)
N20490509: RQ9.1 T9.4(TD_B)
N20490519: RR9.1 T9.1(TD_A)
N20490525: RZ9.2 T9.24(TX_A)
N20490527: J4.28 T9.23(X+_A)
N20490539: J4.25 T9.20(X+_B)
N20490574: J4.27 T9.22(X-_A)
N20490576: RY9.2 T9.21(TX_B)
N20490584: J3.83 T9.9(D-_C)
N20490586: J3.86 T9.8(D+_C)
N20490590: CW9.1 RW9.1
N20490592: CY9.1 RY9.1
N20490594: CX9.1 RX9.1
N20490596: CZ9.1 RZ9.1
N20490598: CA9.1 RO9.2 RP9.2 RQ9.2 RR9.2
N20490696: J4.24 T9.19(X-_B)
N20490712: J3.82 T9.11(D+_D)
N20490726: J3.81 T9.12(D-_D)
N20490768: J3.87 T9.3(D-_A)
N20490804: J3.118 T12.2(D+_A)
N20490808: J4.12 T12.14(X+_D)
N20490812: J4.11 T12.13(X-_D)
N20490828: J4.13 T12.16(X-_C)
N20490830: J3.115 T12.5(D+_B)
N20490841: J3.114 T12.6(D-_B)
N20490843: J4.16 T12.17(X+_C)
N20490859: CB12.1 CW12.2 CX12.2 CY12.2 CZ12.2
N20490885: RQ12.1 T12.4(TD_B)
N20490887: RP12.1 T12.7(TD_C)
N20490889: RO12.1 T12.10(TD_D)
N20490901: J4.18 T12.23(X+_A)
N20490903: RZ12.2 T12.24(TX_A)
N20490909: RR12.1 T12.1(TD_A)
N20490923: J4.15 T12.20(X+_B)
N20490953: RY12.2 T12.21(TX_B)
N20490955: J4.17 T12.22(X-_A)
N20490957: CY12.1 RY12.1
N20490970: CW12.1 RW12.1
N20490974: J3.116 T12.8(D+_C)
N20490976: J3.113 T12.9(D-_C)
N20490986: CA12.1 RO12.2 RP12.2 RQ12.2 RR12.2
N20490996: CZ12.1 RZ12.1
N20490998: CX12.1 RX12.1
N20491088: J4.14 T12.19(X-_B)
N20491098: J3.112 T12.11(D+_D)
N20491130: J3.111 T12.12(D-_D)
N20491159: J3.117 T12.3(D-_A)
N20491179: J3.98 T10.2(D+_A)
N20491183: J4.31 T10.13(X-_D)
N20491189: J4.32 T10.14(X+_D)
N20491193: J3.94 T10.6(D-_B)
N20491195: J3.95 T10.5(D+_B)
N20491197: J4.33 T10.16(X-_C)
N20491216: J4.36 T10.17(X+_C)
N20491230: CB10.1 CW10.2 CX10.2 CY10.2 CZ10.2
N20491260: RO10.1 T10.10(TD_D)
N20491262: RP10.1 T10.7(TD_C)
N20491264: RQ10.1 T10.4(TD_B)
N20491274: RR10.1 T10.1(TD_A)
N20491280: RZ10.2 T10.24(TX_A)
N20491282: J4.38 T10.23(X+_A)
N20491294: J4.35 T10.20(X+_B)
N20491326: J4.37 T10.22(X-_A)
N20491328: RY10.2 T10.21(TX_B)
N20491347: J3.93 T10.9(D-_C)
N20491349: J3.96 T10.8(D+_C)
N20491353: CW10.1 RW10.1
N20491355: CY10.1 RY10.1
N20491357: CX10.1 RX10.1
N20491359: CZ10.1 RZ10.1
N20491361: CA10.1 RO10.2 RP10.2 RQ10.2 RR10.2
N20491453: J4.34 T10.19(X-_B)
N20491475: J3.92 T10.11(D+_D)
N20491481: J3.91 T10.12(D-_D)
N20491523: J3.97 T10.3(D-_A)
N20926605: Q13.1 R20.1
N21773761: CZ4.1 RZ4.1
N21796785: Q2.1 RD2.2 RE2.1
N21798556: Q1.1 RD1.2 RE1.1
N21801215: Q3.1 RD3.2 RE3.1
N21805211: Q12.1 RD12.2 RE12.1
N21806117: Q10.1 RD10.2 RE10.1
N21809256: Q5.1 RD5.2 RE5.1
N21894905: LED7.2 RL7.2
N21894906: LED8.2 RL8.2
N21894907: Q8.2 RL8.1
N21894908: LED10.2 RL10.2
N21894909: Q3.2 RL3.1
N21894913: LED4.2 RL4.2
N21894914: LED5.2 RL5.2
N21894915: LED2.2 RL2.2
N21894917: Q2.2 RL2.1
N21894918: LED6.2 RL6.2
N21894920: Q4.2 RL4.1
N21894921: LED9.2 RL9.2
N21894922: LED3.2 RL3.2
N21894923: Q9.2 RL9.1
N21894924: Q7.2 RL7.1
N21894925: Q14.1 R21.1
N21894926: Q5.2 RL5.1
N21894931: Q6.2 RL6.1
N21894933: LED11.2 RL11.2
N21894935: Q10.2 RL10.1
N21894936: LED12.2 RL12.2
N21894937: Q1.2 RL1.1
N21894938: Q12.2 RL12.1
N21894939: LED1.2 RL1.2
N21894940: Q11.2 RL11.1

Not connected (* = marked no-connect by the designer): J1 9* 12*; J3 124* 125* 126*; J4 124* 125* 126*; J5 1* 6*; J6 1* 6* 9* 10* 11* 12*

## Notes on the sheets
sheet 1
- ANALOG CONNECTIONS
- DIGITAL CONNECTIONS
- POLARITY PROTECTION DIODE, TVS, FUSES TO BE INCLUDED
- POS
- AGND
- DGND
- 51V - 57V
- LITTELFUSE
- OPT
- LO
- ADDRESS
- HI
- MAIN SUPPLY IN
- R8-R11
- R12-R15
- NEG
- LITTELFUSE
- (SDAOUT)
- OPTIONAL PORT LED DRIVERS
- (NC)
- TO DC590
- I2C EXPANSION
- NOTE: UNLESS OTHERWISE SPECIFIED
- 1.  ALL RESISTORS AND CAPACITORS ARE 0603.
- 2.  INSTALL SHUNTS AS SHOWN.
sheet 2
- UPPER ROW
- DATA IN
- DATA/PoE OUT
- DATA IN
- DATA/PoE OUT
- B
- PORT 2
- D
- PORT 4
- DATA IN
- DATA/PoE OUT
- DATA IN
- DATA/PoE OUT
- A
- PORT 1
- C
- PORT 3
- LOWER ROW
sheet 3
- UPPER ROW
- DATA IN
- DATA/PoE OUT
- DATA IN
- DATA/PoE OUT
- F
- PORT 6
- H
- PORT 8
- DATA IN
- DATA/PoE OUT
- DATA IN
- DATA/PoE OUT
- E
- PORT 5
- G
- PORT 7
- LOWER ROW
sheet 4
- UPPER ROW
- DATA IN
- DATA/PoE OUT
- DATA IN
- DATA/PoE OUT
- J
- PORT 10
- L
- PORT 12
- DATA IN
- DATA/PoE OUT
- DATA IN
- DATA/PoE OUT
- I
- PORT 9
- K
- PORT 11
- LOWER ROW
